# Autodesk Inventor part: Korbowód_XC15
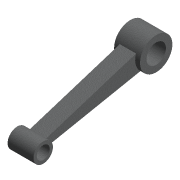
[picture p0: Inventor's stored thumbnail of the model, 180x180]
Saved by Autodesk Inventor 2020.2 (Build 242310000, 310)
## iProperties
Created: 2000-05
Part Number: Korbowód_XC15
Document SubType Name: Modeling
Designer: F.Stasiak
Stock Number: Korbowód_XC15
Density: 7.85 g/cm^3
Material: Stal kuta
Appearance: Aluminium (odlew)
Mass: 1060.98 g
Surface Area: 314.171 cm^2
Volume: 135.156 cm^3
Catalog Web Link: www.expertbooks.pl
Manager: www.cadconsulting.pl
Company: Fabian Stasiak CAD Consulting
Control State: 0
Master: False
Checked Out: False
Shininess: 0.0
Density: 0.0
Volumn: 0.0
Area: 0.0
PropertySet Name: Model Information
Author: F.Stasiak
Subject: Zbiór ćwiczeń. Autodesk Inventor 2020. Kurs Professional
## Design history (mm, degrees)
node "Base1"
node "Bryła1"
node "Korpusy bryłowe"
node "Korpusy powierzchniowe"
